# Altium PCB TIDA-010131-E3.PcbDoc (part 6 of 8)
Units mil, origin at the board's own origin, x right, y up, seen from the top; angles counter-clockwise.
Board outline 6889.76 x 5118.11 mil, 6 copper layers (Top Layer, GND Layer, Signal Layer 1, Signal Layer 2, PWR Layer, Bottom Layer), stack 58.5 mil thick; 758 components, 455 nets, 2194 pads, 1156 vias.
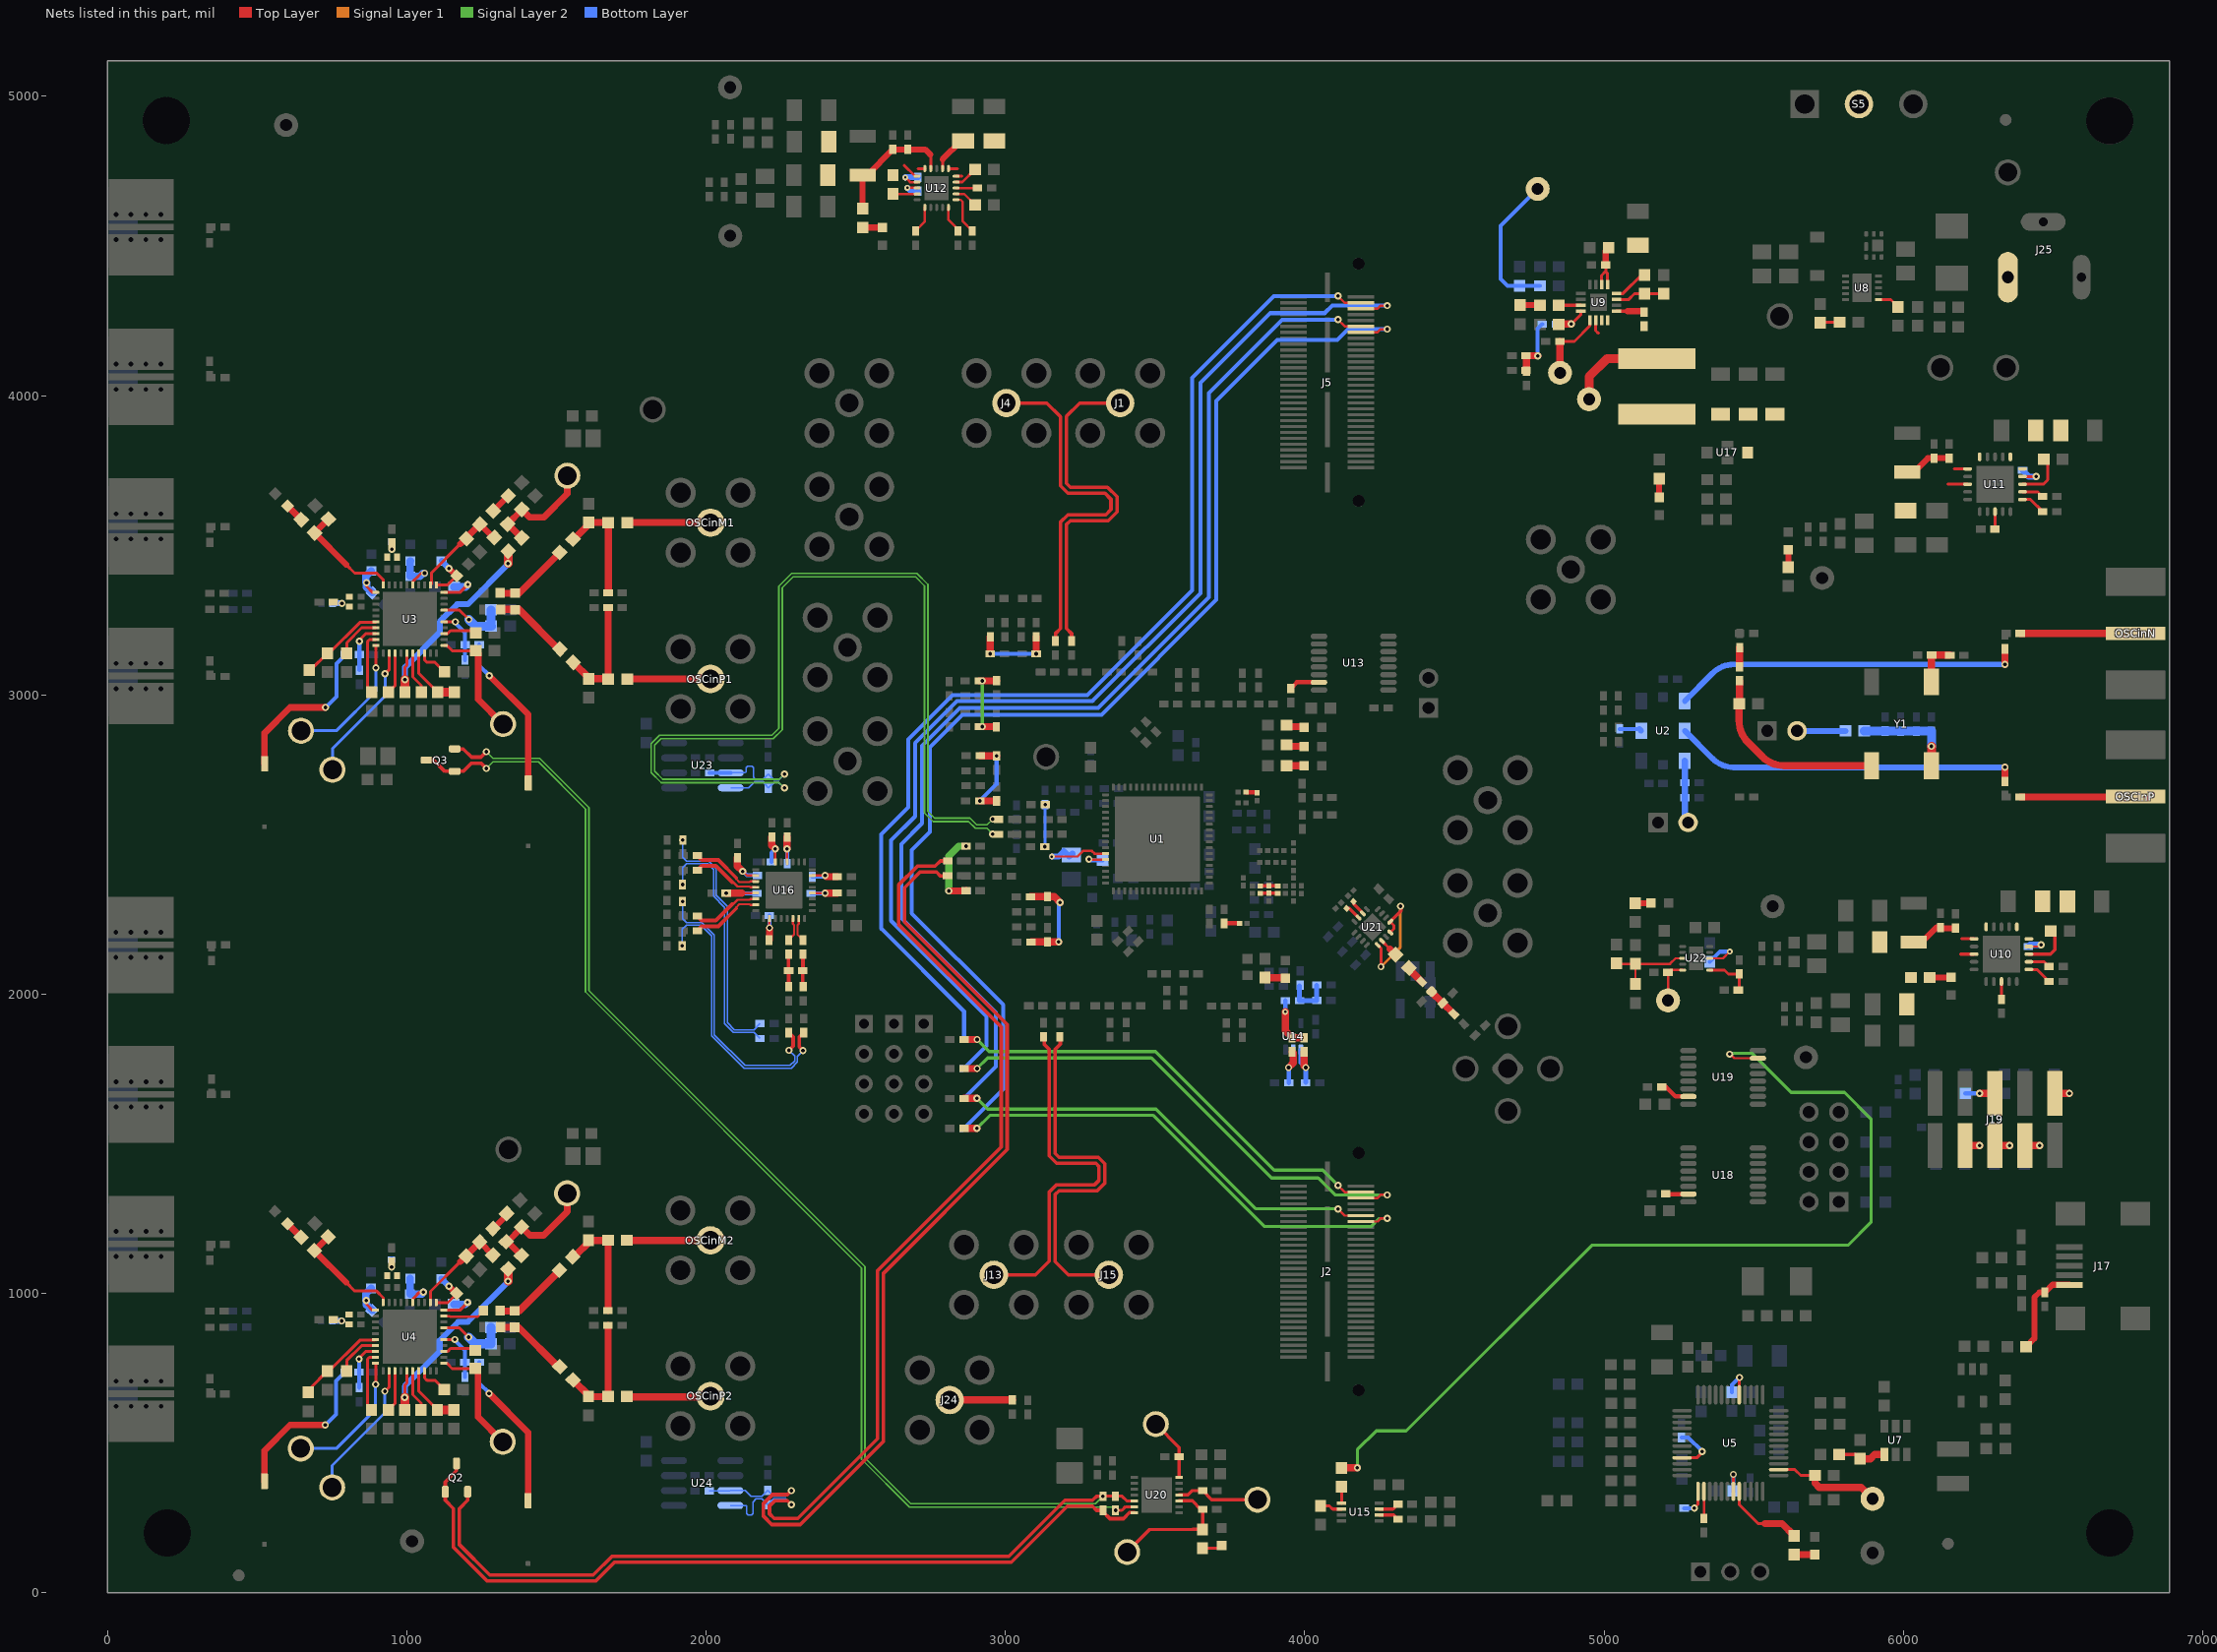
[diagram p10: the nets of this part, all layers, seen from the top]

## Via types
v1: diameter 24, hole 12, Top Layer to Bottom Layer, 726 vias
v2: diameter 32, hole 16, Top Layer to Bottom Layer, 311 vias
v3: diameter 19.68, hole 7.87, Top Layer to Bottom Layer, 117 vias
v4: diameter 25, hole 10, Top Layer to Bottom Layer, 2 vias

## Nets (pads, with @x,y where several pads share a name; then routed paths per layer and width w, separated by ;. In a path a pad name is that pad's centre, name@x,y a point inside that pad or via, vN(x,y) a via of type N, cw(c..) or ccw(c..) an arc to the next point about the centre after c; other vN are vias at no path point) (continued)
LMX_OSCIN2-: C105.2 U4.9 | length 141.3
  Top Layer w8: U4.9@1124.62,924.04 1143.43,924.04 1145.27,922.2 1236.66,922.2 C105.2@1256.79,942.32
LMX_SDO: R207.2 U19.7 | length 3154.5
  Top Layer w8: v1@5419,1802 5435.02,1785.98 U19.7@5514.14,1785.98
  Top Layer w24: R207.2@4123,417.5 4123.5,418 v1(4176,418)
  Signal Layer 2 w10.5: v1(4176,418) 4176,478 4239,541 4339,541 4959,1161 5815,1161 5892,1238 5892,1583 5803.5,1671.5 5625.5,1671.5 5495,1802 v1@5419,1802
  other v1: 5420,1799.5
MUXOUT1: R102.1 R105.2 U3.20 | length 376.8
  Top Layer w9.84: 797.65,3435.55 826.65,3406.55 899.65,3406.55 922.12,3384.07 U3.20@922.12,3367.72
  Top Layer w22: R102.1@738.48,3587.3 R105.2@692.19,3541.01 797.65,3435.55
MUXOUT2: R135.1 R136.2 U4.20 | length 376.8
  Top Layer w9.84: 797.39,1037.14 826.39,1008.14 899.39,1008.14 921.86,985.67 U4.20@921.86,969.32
  Top Layer w22: R135.1@738.22,1188.9 691.93,1142.61 797.39,1037.14
NetC8_2: C8.2 R28.2 | length 37.8
  Top Layer w8: R28.2@3838.57,2674.78 R28.2@3840.57,2672.77
  Top Layer w15: C8.2@3803.57,2674.78 R28.2@3838.57,2674.78
NetC10_2: C10.2 C19.2 C176.2 C177.2 L36.1 Y1.4 | length 340.1
  Top Layer w30: Y1.4@6093.97,2763.39 v1(6093.97,2828.39)
  Bottom Layer w30: L36.1@5869.47,2879.39 5938.73,2879.39 C177.2@5938.97,2879.15 5990.6,2879.15 C176.2@5990.97,2878.77 C19.2@6043.97,2878.77 C10.2@6093.97,2878.77 v1(6093.97,2828.39)
NetC13_1: C13.1 U1.11 | length 281.5
  Top Layer w8: v3@3155,2460 3241,2460 3259.66,2478.66 3288.97,2478.66 3298.23,2469.4 U1.11@3334.6,2469.4
  Bottom Layer w20: v3@3155,2460 3177.79,2460 3195.45,2477.66 3212.45,2460.66 3218.57,2466.78 C13.1@3220.57,2464.78 cw(c3225.07,2464.78) C13.1@3225.07,2469.28
  other v3: 3155,2459.69
NetC14_1: C14.1 U1.12 | length 110.7
  Top Layer w8: v1(3279.07,2451.28) 3279.07,2455.78 3279.57,2456.28 3286.14,2449.72 U1.12@3334.6,2449.72
  Bottom Layer w13.5: v1(3279.07,2451.28) 3282.97,2447.39 C14.1@3325.23,2447.39
NetC17_1: C17.1 R52.2 | length 51
  Top Layer w15: C17.1@3730.86,2236.53 R52.2@3781.84,2236.53
NetC27_1: C27.1 R72.1 R227.2 | length 58.1
  Top Layer w12: C27.1@3851.99,2337.19 3880.79,2337.19 R72.1@3881,2336.98 R227.2@3910.01,2336.99
NetC29_1: C29.1 R271.2 R273.2 | length 58.1
  Top Layer w12: C29.1@3851.99,2361.79 3880.79,2361.79 R273.2@3881,2362 R271.2@3910.01,2361.99
NetC40_1: C40.1 C129.1 L34.1 R226.1 U9.1 U9.2 U9.16 | length 298.7
  Top Layer w9.84: U9.2@4991.82,4371.11 4991.82,4401.04 5005.6,4414.82 C40.1@5005.6,4436.66
  Top Layer w10: 5005.6,4414.82 5011.52,4408.89 U9.1@5011.52,4371.11 ; U9.16@5041.47,4341.16 5063.44,4341.16 5125.44,4403.16 R226.1@5135.97,4403.16
  Top Layer w20: C40.1@5005.6,4436.66 5005.6,4483.79 C129.1@5015.47,4493.66
NetC41_1: C41.1 U9.13 | length 93.7
  Top Layer w10: U9.13@5041.47,4282.06 5078.57,4282.06
  Top Layer w20: 5078.57,4282.06 5131.2,4282.06 C41.1@5133.97,4279.28
NetC41_2: C41.2 L35.1 TP13.1 U9.10 U9.11 U9.12 | length 474.4
  Top Layer w10: U9.10@4972.12,4252.11 4972.12,4217.4 4981.09,4208.44
  Top Layer w30: TP13.1@4950,3988 4950,4063 5010.57,4123.57 L35.1@5176.97,4123.57 L35.1@5276.89,4123.57
NetC42_1: C42.1 C43.1 C73.1 L35.2 U17.1
NetC45_2: C45.2 L11.2 R82.2 R86.2 | length 31.3
  Bottom Layer w20: L11.2@752.31,3305.97 v1(783.6,3305.97)
NetC46_2: C46.2 R83.2 U3.7 | length 233.5
  Top Layer w9.84: U3.7@1124.88,3283.07 1176.5,3283.07 v1(1207.6,3251.97)
  Bottom Layer w30: v1(1207.6,3251.97) 1229.73,3229.85 C46.2@1282.31,3229.85 1282.22,3229.94 R83.2@1282.22,3283.79
NetC47_2: C47.2 R85.2 U3.11 | length 159.7
  Top Layer w10: U3.11@1099.29,3367.72 1137.18,3367.72 C47.2@1173.22,3403.76
  Top Layer w20: v1(1141.53,3422.42) C47.2@1166.65,3397.29
  Bottom Layer w20: R85.2@1116.6,3447.41 1116.6,3447.34 v1(1141.53,3422.42)
NetC49_1: C49.1 R88.2 U3.15 | length 166
  Top Layer w9.84: U3.15@1020.55,3367.72 1020.55,3378.6 1024.39,3382.44 1024.39,3382.9 1031.94,3390.45 1032.4,3390.45 1048.51,3406.56 v1(1059.56,3406.56)
  Bottom Layer w25: R88.2@1012.37,3447.49 1011.7,3446.82 C49.1@1011.7,3395.8 1043.82,3395.8 v1@1054.6,3406.59 ; v1@1054.64,3406.56 v1(1059.56,3406.56)
NetC50_2: C50.2 R87.2 U3.21 | length 141
  Top Layer w10: v1(865.7,3374.55) 865.7,3362.49 886.07,3342.13 U3.21@896.53,3342.13
  Bottom Layer w25: R87.2@881.7,3414.79 863.84,3396.92 863.84,3376.41 v1(865.7,3374.55) 865.7,3360.55 C50.2@885.02,3341.23
NetC55_2: C55.2 R89.1 U3.26 | length 291.3
  Top Layer w9.84: R89.1@671.6,3083.46 679.6,3083.46 C55.2@735.6,3139.46 741.1,3139.46 843.55,3241.91 894.74,3241.91 U3.26@896.53,3243.7
NetC56_2: C56.2 R91.1 U3.37 | length 211.9
  Top Layer w9.84: U3.37@1040.23,3139.37 1040.23,3072.01 C56.2@1103.4,3008.84
  Top Layer w30: C56.2@1103.4,3008.84 R91.1@1158.6,3008.84
NetC58_2: C58.2 R94.1 U3.35 | length 725.3
  Top Layer w9.84: v1(994.1,3050.97) 994.1,3092.21 1000.86,3098.97 U3.35@1000.86,3139.37
  Top Layer w30: C58.2@994.1,3008.84 v1(994.1,3050.97) ; v1@1339.43,3439.71 R94.1@1339.43,3480.07
  Bottom Layer w20: v1(994.1,3050.97) 994.1,3092.54 1110.52,3208.95 1110.52,3244.41 1169,3302.9 1204.46,3302.9 1338.74,3437.17 v1(1338.74,3439.01)
NetC59_1: C59.1 R94.2 R95.2 Vtune_TP1.1 | length 391.6
  Top Layer w22: R94.2@1383.98,3524.62 1337.98,3570.62 R95.2@1337.08,3570.62 1384.43,3617.97 C59.1@1384.43,3620.07 1411.54,3592.97 1457.6,3592.97 1536.7,3672.07 Vtune_TP1.1@1536.7,3732.35
NetC60_1: C60.1 C62.1 R95.1 U3.12 | length 327
  Top Layer w10: U3.12@1079.6,3367.72 1082.56,3370.68 1082.56,3407.92 1179.38,3504.74
  Top Layer w20: C60.1@1244.43,3570.07 R95.1@1288.43,3526.07
  Top Layer w22: 1179.38,3504.74 C60.1@1237.6,3562.97
  Top Layer w30: R95.1@1288.43,3526.07 R95.1@1292.53,3526.07
NetC60_2: C60.2 R96.1 | length 71.1
  Top Layer w20: C60.2@1288.98,3614.62 R96.1@1339.06,3664.7
  Top Layer w30: R96.1@1339.06,3664.7 R96.1@1339.33,3664.7
NetC61_2: C61.2 L12.2 R93.1 R97.2 | length 26
  Bottom Layer w20: v1(950.28,3486.06) L12.2@950.28,3512.05
NetC63_2: C63.2 U3.10 | length 138.8
  Top Layer w10: U3.10@1124.88,3342.13 1177.59,3342.13 v4(1203.7,3368.25)
  Bottom Layer w25: C63.2@1157.7,3360.69 1196.15,3360.69 v4(1203.7,3368.25)
NetC65_1: C65.1 U3.36 | length 142.1
  Top Layer w9.84: U3.36@1020.55,3139.37 1020.55,3060.03 1048.5,3032.07 C65.1@1048.5,3008.84
NetC66_2: C66.2 U3.38 | length 105.8
  Top Layer w9.84: U3.38@1059.92,3139.37 1059.92,3116.28 1067.65,3108.55 1094.61,3108.55 C66.2@1126.31,3076.85
NetC67_1: C67.1 U3.29 | length 211
  Top Layer w9.84: C67.1@883,3008.84 872.73,3008.84 869.6,3011.97 869.6,3178.97 875.28,3184.65 U3.29@896.53,3184.65
NetC68_1: C68.1 U3.3 | length 116.7
  Top Layer w9.84: U3.3@1124.88,3204.33 1136.22,3204.33 1146.35,3214.47 1223.09,3214.47 C68.1@1230.21,3207.35 C68.1@1227.2,3204.33
NetC69_2: C69.2 U3.27 | length 152.5
  Top Layer w9.84: C69.2@799.7,3139.05 799.7,3174.07 849.65,3224.02 U3.27@896.53,3224.02
NetC70_2: C70.2 U3.33 | length 139.7
  Top Layer w9.84: C70.2@939.4,3008.84 961.49,3030.93 U3.33@961.49,3139.37
NetC71_1: C71.1 R107.2 R109.2 | length 252.3
  Top Layer w24: C71.1@1313.86,3285.55 1374.26,3285.55 R107.2@1509.99,3149.82
NetC72_1: C72.1 R109.1 R112.1 | length 251.9
  Top Layer w24: C72.1@1312.16,3340.72 1313.66,3339.22 1375.26,3339.22 R112.1@1508.31,3472.27
NetC74_1: C74.1 TP15.1 U9.9 | length 245.9
  Top Layer w10: C74.1@4852.62,4181 4901,4181 4952.42,4232.42 U9.9@4952.42,4252.11
  Top Layer w24: C74.1@4852.62,4181 4852.62,4076.38 TP15.1@4853,4076
NetC75_1: C75.1 R231.1 | length 65.7
  Top Layer w20: C75.1@4719.97,4302.16 4784.98,4302.16 R231.1@4785.48,4301.66
NetC78_2: C78.2 L13.2 R115.2 R119.2 | length 31.3
  Bottom Layer w20: L13.2@751.55,908.07 v1(782.85,908.07)
NetC79_2: C79.2 R116.2 U4.7 | length 233.5
  Top Layer w9.84: U4.7@1124.62,884.67 1176.24,884.67 v1(1206.85,854.07) v1@1207.35,853.57
  Bottom Layer w30: v1(1206.85,854.07) 1228.97,831.94 C79.2@1281.55,831.94 1281.46,832.04 R116.2@1281.46,885.89
NetC80_2: C80.2 R118.2 U4.11 | length 159.7
  Top Layer w10: U4.11@1099.03,969.32 1136.92,969.32 C80.2@1172.96,1005.36
  Top Layer w20: v1@1141.27,1024.02 C80.2@1166.39,998.89
  Bottom Layer w20: R118.2@1115.85,1049.51 R118.2@1115.85,1049.44 v1(1140.77,1024.52)
NetC82_1: C82.1 R121.2 U4.15 | length 156.8
  Top Layer w9.84: U4.15@1020.29,969.32 1020.29,981.25 1023.63,984.6 1023.63,985 1042.63,1004 v1(1056,1004)
  Bottom Layer w25: R121.2@1011.62,1049.59 1010.95,1048.92 C82.1@1010.95,997.9 1049.9,997.9 v1(1056,1004)
NetC83_2: C83.2 R120.2 U4.21 | length 141
  Top Layer w10: v1@865.45,976.14 865.45,964.09 885.81,943.73 U4.21@896.27,943.73
  Bottom Layer w25: R120.2@880.95,1016.88 863.08,999.02 863.08,978.51 v1(864.95,976.64) 864.95,962.64 C83.2@884.26,943.33
NetC88_2: C88.2 R122.1 U4.26 | length 291.3
  Top Layer w9.84: R122.1@671.35,685.06 679.35,685.06 735.35,741.06 740.84,741.06 843.29,843.51 894.48,843.51 U4.26@896.27,845.3
NetC89_2: C89.2 R124.1 U4.37 | length 211.9
  Top Layer w9.84: U4.37@1039.97,740.97 1039.97,673.61 C89.2@1103.15,610.44
  Top Layer w30: C89.2@1103.15,610.44 R124.1@1158.35,610.44
NetC91_2: C91.2 R127.1 U4.35 | length 722.9
  Top Layer w9.84: v1@993.85,652.57 993.85,693.81 1000.6,700.57 U4.35@1000.6,740.97
  Top Layer w30: C91.2@993.85,610.44 v1@993.85,652.57 ; v1@1339.17,1041.31 R127.1@1339.17,1081.67
  Bottom Layer w20: v1(993.35,653.07) 993.35,689.97 1109.76,806.38 1109.76,842.51 1172.24,905 1203.7,905 1337.98,1039.27 v1(1337.98,1041.11)
NetC92_1: C92.1 R127.2 R128.2 Vtune_TP2.1 | length 391.6
  Top Layer w22: R127.2@1383.72,1126.22 1337.72,1172.22 1336.82,1172.22 1384.17,1219.57 1384.17,1221.67 1411.28,1194.57 1457.35,1194.57 1536.45,1273.67 Vtune_TP2.1@1536.45,1333.94
NetC93_1: C93.1 C95.1 R128.1 U4.12 | length 327
  Top Layer w10: U4.12@1079.34,969.32 1079.34,1006.56 1179.12,1106.34
  Top Layer w20: C93.1@1244.17,1171.67 R128.1@1287.67,1128.17 R128.1@1288.17,1127.67
  Top Layer w22: 1179.12,1106.34 C93.1@1237.35,1164.57
  Top Layer w30: R128.1@1288.17,1127.67 R128.1@1292.27,1127.67
NetC93_2: C93.2 R129.1 | length 71.1
  Top Layer w20: C93.2@1288.72,1216.22 R129.1@1338.8,1266.3
  Top Layer w30: R129.1@1338.8,1266.3 R129.1@1339.07,1266.3
NetC94_2: C94.2 L14.2 R126.1 R130.2 | length 26
  Bottom Layer w20: v1(949.52,1088.16) L14.2@949.52,1114.15
NetC96_2: C96.2 U4.10 | length 138.8
  Top Layer w10: U4.10@1124.62,943.73 1177.33,943.73 v4@1203.45,969.84
  Bottom Layer w25: C96.2@1156.94,962.79 1195.39,962.79 v4(1202.95,970.34)
NetC98_1: C98.1 U4.36 | length 142.1
  Top Layer w9.84: U4.36@1020.29,740.97 1020.29,661.62 1048.25,633.67 C98.1@1048.25,610.44
NetC99_2: C99.2 U4.38 | length 105.8
  Top Layer w9.84: U4.38@1059.66,740.97 1059.66,717.88 1067.39,710.14 1094.35,710.14 C99.2@1126.05,678.44
NetC100_1: C100.1 U4.29 | length 211
  Top Layer w9.84: C100.1@882.75,610.44 872.47,610.44 869.35,613.57 869.35,780.57 875.03,786.25 U4.29@896.27,786.25
NetC101_1: C101.1 U4.3 | length 116.7
  Top Layer w9.84: U4.3@1124.62,805.93 1135.96,805.93 1146.09,816.07 1222.83,816.07 1229.95,808.94 C101.1@1226.94,805.93
NetC102_2: C102.2 U4.27 | length 152.5
  Top Layer w9.84: C102.2@799.45,740.65 799.45,775.67 849.4,825.62 U4.27@896.27,825.62
NetC103_2: C103.2 U4.33 | length 139.7
  Top Layer w9.84: C103.2@939.15,610.44 961.23,632.53 U4.33@961.23,740.97
NetC104_1: C104.1 R140.2 R142.2 | length 252.3
  Top Layer w24: C104.1@1313.6,887.14 1374,887.14 R140.2@1509.73,751.42
NetC105_1: C105.1 R142.1 R145.1 | length 251.9
  Top Layer w24: C105.1@1311.9,942.32 1313.4,940.82 1375,940.82 R145.1@1508.06,1073.87
NetC113_2: C113.2 U5.38 VCCCORE.1 | length 369
  Top Layer w10: U5.38@5583.62,411.44 5637.78,411.44 5657.2,392.02 C113.2@5704.7,392.02
  Top Layer w24: C113.2@5704.7,392.02 5704.7,366.27 5718.96,352.02 5859.2,352.02 VCCCORE.1@5897.2,314.02
NetC122_1: C122.1 J17.1 R148.1 | length 310.6
  Top Layer w20: R148.1@6410.5,822 6438,849.5 6438,987.09 6454.54,1003.62 C122.1@6473,1003.62 6498.39,1029.01 J17.1@6554.77,1029.01
NetC133_1: C133.1 U8.1 | length 74.9
  Top Layer w10: U8.1@5917.3,4320.64 5958.05,4320.64 C133.1@5982.18,4296.51
NetC134_1: C134.1 L28.1 L30.2 U10.13 U10.15 U10.16 | length 161.9
  Top Layer w12: U10.13@6419.43,2133.66 6491.94,2133.66 6506.57,2148.29 6506.57,2197.32 C134.1@6492.64,2211.25
NetC135_1: C135.1 C136.1 C137.1 L20.1 L23.1 R223.2 U10.1 U10.3 U10.20 | length 246.5
  Top Layer w10: 6191.34,2133.66 U10.3@6236.36,2133.66 ; 6195.69,2184.84 U10.1@6236.36,2184.84
  Top Layer w20: C137.1@6034.43,2174.29 6062.39,2174.29 6110.72,2222.62 C136.1@6124.43,2222.62 6126.42,2220.63 C135.1@6174.43,2220.63
NetC138_1: C138.1 L29.1 L31.2 U11.13 U11.15 U11.16 | length 165.1
  Top Layer w10: U11.13@6398,3703.91 6467.99,3703.91 6482.69,3718.61 6482.69,3774.31 C138.1@6469.5,3787.5
NetC139_1: C139.1 C140.1 C141.1 L21.1 U11.1 U11.3 U11.20 | length 270.3
  Top Layer w10: 6148.54,3703.91 U11.3@6214.93,3703.91 ; 6170.19,3755.09 U11.1@6214.93,3755.09
  Top Layer w20: C141.1@6013,3744.54 6035.98,3744.54 6082.32,3790.88 C140.1@6103,3790.88 C139.1@6153,3790.88
NetC150_1: C150.1 U10.14 | length 87.3
  Top Layer w8: U10.14@6419.43,2159.25 6454.25,2159.25 v1(6460,2165)
  Bottom Layer w20: C150.1@6418.06,2159.25 6423.81,2165 v1(6460,2165)
NetC151_1: C151.1 U11.14 | length 99.9
  Top Layer w10: U11.14@6398,3729.5 v1(6444,3729.5)
  Bottom Layer w20: C151.1@6398.62,3750 6419.12,3729.5 v1(6444,3729.5)
NetC154_1: C154.1 L32.1 L33.2 U12.14 U12.15 U12.16 U12.17 | length 254.7
  Top Layer w10: U12.17@2790.15,4758.63 2790.15,4789.73 ; U12.16@2809.83,4758.63 2840.07,4758.63 ; U12.14@2835.42,4713.35 2856.6,4713.35 C154.1@2898.5,4755.26 ; U12.15@2835.42,4733.04 2854.04,4733.04
  Top Layer w20: 2790.15,4789.73 2851.59,4851.17 L32.1@2859,4851.17
NetC155_1: C155.1 C156.1 C157.1 C162.1 L25.1 L27.1 R224.2 R294.2 U12.1 U12.2 U12.19 U12.20 | length 598.1
  Top Layer w8: v3(2665.79,4729.15) 2681.59,4713.35 U12.2@2705.5,4713.35
  Top Layer w9.84: 2662,4769.37 2698.33,4733.04 U12.1@2705.5,4733.04 ; 2748.72,4805.98 2750.78,4803.92 U12.19@2750.78,4758.63
  Top Layer w10: 2708.46,4758.63 U12.20@2731.09,4758.63
  Top Layer w20: R224.2@2523,4624.5 C157.1@2523,4736.3 2537.66,4736.3 C156.1@2624,4822.64 C155.1@2674,4822.64 2732.06,4822.64 2748.72,4805.98
  Bottom Layer w20: v3(2665.79,4729.15) 2666.41,4729.78 C162.1@2707.79,4729.78
NetC162_2: C162.2 U12.3 | length 72.7
  Top Layer w8: v3(2672.79,4694.15) 2705.02,4694.15 U12.3@2705.5,4693.67
  Bottom Layer w20: v3(2672.79,4694.15) 2684.41,4682.53 C162.2@2707.79,4682.53
NetC166_1: C166.1 R233.1 U16.2 | length 155.8
  Top Layer w8: v1(2122.82,2410.41) 2136.62,2396.61 U16.2@2166.12,2396.61
  Top Layer w24: R233.1@2104.82,2455.78 2104.82,2428.41 v1(2122.82,2410.41)
  Bottom Layer w13.5: v1(2122.82,2410.41) 2136.32,2396.91 C166.1@2171.2,2396.91
NetC167_2: C167.2 R239.1 U16.10 | length 113.8
  Top Layer w8: U16.10@2211.39,2252.91 2211.39,2221.83 v1(2211.82,2221.41)
  Top Layer w24: R239.1@2210.82,2180.53 2211.82,2181.53 v1(2211.82,2221.41)
  Bottom Layer w13.5: v1(2211.82,2221.41) C167.2@2211.82,2262.28
NetC168_1: C168.1 R234.1 U16.5 | length 201.7
  Top Layer w8: 2118.96,2337.55 U16.5@2166.12,2337.55
  Top Layer w24: v1(2067.44,2337.41) 2067.59,2337.55 2118.96,2337.55
  Bottom Layer w13.5: v1(2067.44,2337.41) 2067.94,2336.91 C168.1@2170.2,2336.91
NetC169_2: C169.2 R238.1 U16.28 | length 133.4
  Top Layer w8: U16.28@2270.45,2441.88 2270.45,2485.04 v1(2270.82,2485.41)
  Top Layer w24: v1(2270.82,2485.41) R238.1@2270.82,2525.28
  Bottom Layer w13.5: C169.2@2270.82,2435.53 v1(2270.82,2485.41)
NetC170_1: C170.1 R235.1 U16.20 | length 129.7
  Top Layer w8: U16.20@2355.09,2337.55 v1(2397.62,2337.55)
  Top Layer w24: v1(2397.62,2337.55) 2397.97,2337.91 R235.1@2438.2,2337.91
  Bottom Layer w13.5: C170.1@2351.44,2336.91 2396.97,2336.91 v1(2397.62,2337.55)
NetC171_1: C171.1 R236.1 U16.23 | length 128.8
  Top Layer w6.5: v1(2397.62,2396.61) v1@2401.32,2392.91
  Top Layer w8: U16.23@2355.09,2396.61 v1(2397.62,2396.61)
  Top Layer w24: v1@2401.32,2392.91 R236.1@2438.2,2392.91
  Bottom Layer w4.25: v1@2393.68,2392.67 v1(2397.62,2396.61)
  Bottom Layer w13.5: C171.1@2355.09,2392.67 v1@2393.68,2392.67
NetC172_1: C172.1 R237.1 U16.30 | length 136.7
  Top Layer w8: U16.30@2231.08,2441.88 v1@2231.08,2485.04
  Top Layer w24: R237.1@2219.82,2524.78 2219.82,2497.04 v1(2231.45,2485.41)
  Bottom Layer w13.5: C172.1@2218.44,2441.41 2218.44,2472.4 v1(2231.45,2485.41)
NetC173_1: C173.1 R244.2 R249.2 | length 109.1
  Top Layer w12: R244.2@2275.82,2024.53 2276.2,2024.91 R249.2@2276.2,2078.91 2275.82,2079.28 C173.1@2275.82,2133.28
NetC173_2: C173.2 U16.14 | length 81.3
  Top Layer w7: C173.2@2275.82,2180.53 2293.73,2198.44 2293.73,2231 2290.13,2234.59 U16.14@2290.13,2252.91
NetC174_1: C174.1 R249.1 R250.2 | length 109.5
  Top Layer w12: C174.1@2323.82,2133.28 2323.82,2079.28 R249.1@2323.44,2078.91 2323.44,2025.91 R250.2@2324.82,2024.53
NetC174_2: C174.2 U16.15 | length 81.2
  Top Layer w7: U16.15@2309.82,2252.91 2309.82,2234.59 2306.23,2231 2306.23,2198.12 C174.2@2323.82,2180.53
NetC175_1: C175.1 R232.2 U9.8 | length 151.1
  Top Layer w10: R232.2@4848.47,4237.66 R232.2@4849.97,4237.66 ; v1(4891,4239) 4922.47,4270.47 U9.8@4922.47,4282.06
  Top Layer w24: R232.2@4848.47,4237.66 4849.81,4239 v1(4891,4239)
  Bottom Layer w13.5: C175.1@4840.62,4239 v1(4891,4239)
NetC175_2: C175.2 R259.1 R260.2 R261.1 | length 203
  Top Layer w15: R259.1@4739.62,4133 R259.1@4741,4131.62
  Top Layer w24: R259.1@4739.62,4133 v1(4778.32,4132.97) ; R260.2@4741,4081.62 R259.1@4741,4131.62
  Bottom Layer w13.5: v1(4778.32,4132.97) 4778.32,4223.94 C175.2@4793.38,4239
NetC178_2: C178.2 R299.1 Y1.1 | length 151.3
  Top Layer w24: Y1.1@6093.97,3043.39 6093.97,3132.77 C178.2@6094.6,3133.39 6154.62,3133.39 R299.1@6155.35,3132.66
NetC179_1: C179.1 R33.1 | length 64.1
  Top Layer w24: R33.1@5452.97,3094.28 5453.07,3094.38 C179.1@5453.07,3158.37
NetC180_2: C180.2 U12.12 | length 78.2
  Top Layer w8: U12.12@2835.42,4673.98 2862.02,4673.98 C180.2@2898.5,4637.5
NetC181_2: C181.2 U12.13 | length 71
  Top Layer w8: U12.13@2835.42,4693.67 2906.21,4693.67 C181.2@2906.38,4693.5
NetC187_2: C187.2 C188.2 J16.2 U2.6@5269.91,2779.81 | length 206.3
  Bottom Layer w20: U2.6@5269.91,2779.81 5270.35,2779.36 C188.2@5270.35,2706.66 C187.2@5270.35,2656.66 J16.2@5270.35,2573.66
NetC203_1: C203.1 Q2.1 Q2.3 U20.7 | length 2760
  Top Layer w12: Q2.3@1166.1,432 1166.1,407.76 1128.7,370.36 Q2.1@1128.7,337.51 1128.7,308.83 1156.1,281.43 1156.1,249.76 1156.1,151.9 1269,39 1631.28,39 1694.28,102 3020.28,102 3207.28,289 3291.57,289 3305.19,275.38 C203.1@3326,275.38 3326,271 3349.37,247.63 3394.63,247.63 3414.74,267.74 U20.7@3430.77,267.74
NetC203_2: C203.2 C204.2 Q2.2 Q3.2 U20.5 | length 6568.6
  Top Layer w9.8: C203.2@3326,322.62 C204.2@3368,322.62 3389.88,322.62 3405.39,307.11 U20.5@3430.77,307.11
  Top Layer w12: Q3.2@1160.24,2819.4 1188.93,2819.4 1216.33,2792 1248,2792 v1(1266,2810) ; Q2.2@1203.5,337.51 1203.5,308.83 1176.1,281.43 1176.1,160.19 1277.28,59 1623,59 1686,122 3012,122 3199,309 3291.57,309 3305.19,322.62 C203.2@3326,322.62
  Signal Layer 2 w5.5: v1(1266,2810) 1288.25,2787.75 1444.51,2787.75 1608.5,2623.76 1608.5,2012.5 2531,1090 2531,451 2684,298 3301.31,298 v1(3326,322.69)
NetC204_1: C204.1 Q3.1 Q3.3 U20.6 | length 4181.9
  Top Layer w7: v1(3368,275.45) v1(3368,275.45)
  Top Layer w9.8: v1(3368,275.45) 3389.38,275.38 3401.43,287.43 U20.6@3430.77,287.43
  Top Layer w12: Q3.3@1065.76,2782 1090,2782 1127.4,2744.6 1188.93,2744.6 1216.33,2772 1248,2772 v1(1266,2754)
  Signal Layer 2 w5.5: v1(1266,2754) 1288.25,2776.25 1439.75,2776.25 1597,2619 1597,2007.74 2519.5,1085.24 2519.5,446.24 2679.24,286.5 3356.95,286.5 v1(3368,275.45)
NetC207_1: C207.1 R331.1 R332.2 U22.3 | length 296.7
  Top Layer w8: R331.1@5042,2102.5 5043,2101.5 C207.1@5105,2101.5 ; R332.2@5105,2033.5 C207.1@5105,2101.5 ; U22.3@5262.72,2119.8 5238.8,2119.8 5220.5,2101.5 C207.1@5105,2101.5
NetC208_1: C208.1 U22.8 | length 156.8
  Top Layer w8: U22.8@5353.27,2119.8 5397.8,2119.8 v3(5420,2142)
  Bottom Layer w13.5: C208.1@5353.27,2107.99 5387.28,2142 v3(5420,2142)
NetC210_1: C210.1 R322.1 | length 64.6
  Top Layer w24: C210.1@4349.27,2087.73 C210.1@4348.27,2087.73 4348.27,2084.08 R322.1@4390.64,2041.71
NetC210_2: C210.2 U21.2 | length 64.7
  Top Layer w10: U21.2@4258.01,2178.07 4285,2151.08 4285,2151
  Top Layer w24: 4285,2151 C210.2@4303.73,2132.27
NetCE_TP1_1: CE_TP1.1 R90.2 U3.1 | length 395.5
  Top Layer w9.84: U3.1@1124.88,3164.96 1134.61,3164.96 1152.23,3147.35 R90.2@1230.21,3147.35
  Top Layer w22: R90.2@1230.21,3147.35 1239,3138.55 1239,2985.05 CE_TP1.1@1321.7,2902.35
NetCE_TP2_1: CE_TP2.1 R123.2 U4.1 | length 400.2
  Top Layer w9.84: U4.1@1124.62,766.56 1134.35,766.56 1151.97,748.94 R123.2@1238,748.94
  Top Layer w22: R123.2@1238,748.94 1238,587.39 CE_TP2.1@1320.95,504.44 CE_TP2.1@1321.45,503.94
NetD1_1: D1.1 R77.2 | length 61
  Top Layer w24: R77.2@3939.53,2832.95 3944.47,2828 D1.1@3998.47,2828
NetD2_1: D2.1 R78.2 | length 59
  Top Layer w24: R78.2@3937.48,2893.78 D2.1@3996.46,2893.78
NetD3_1: D3.1 R79.2 | length 68.8
  Top Layer w24: R79.2@3867.19,2054.9 3933.16,2054.9 D3.1@3935.19,2052.87
NetD4_1: D4.1 R80.2 | length 59
  Top Layer w24: R80.2@3939.37,2763.58 D4.1@3998.34,2763.58
NetD5_1: D5.1 R105.1 | length 64
  Top Layer w22: D5.1@602.41,3630.79 R105.1@647.65,3585.55
NetD6_1: D6.1 R136.1 | length 64
  Top Layer w22: D6.1@602.15,1232.39 R136.1@647.39,1187.15
NetD10_1: D10.1 R217.1 | length 69
  Top Layer w24: R217.1@5635.2,127.52 D10.1@5704.17,127.52
NetD11_1: D11.1 R220.1 | length 63
  Top Layer w20: D11.1@5184.3,3659.87 R220.1@5184.3,3722.85
NetD13_1: D13.1 R222.1 | length 59
  Top Layer w20: R222.1@5615.85,3426.48 D13.1@5615.85,3485.45
NetD14_1: D14.1 R223.1 | length 71.2
  Top Layer w20: R223.1@6088.36,2055.48 6158.84,2055.48 D14.1@6159.36,2056.01
NetD15_1: D15.1 R224.1 | length 66.7
  Top Layer w20: R224.1@2523,4561.5 2589.13,4561.5 D15.1@2589.5,4561.13
NetD16_2: D16.2 R319.2 | length 67.5
  Top Layer w11: R319.2@3658.51,148.74 3714.02,148.74 D16.2@3722.51,157.24
NetD17_1: D17.1 R342.1 | length 52.7
  Top Layer w20: R342.1@5104,2304.5 5155.98,2304.5 D17.1@5156.47,2304
NetJ1_1: J1.1 R3.1 | length 1242.3
  Top Layer w12: R3.1@3221.17,3180.02 3221.17,3204.77 3204.27,3221.67 3204.27,3569.46 3216.82,3582 3344,3582 3373,3611 3373,3662 3341,3694 3216.82,3694 3204.27,3706.54 3204.27,3930.77 3248.5,3975 J1.1@3383.5,3975
NetJ2_4: J2.4 R252.2 | length 1537.4
  Top Layer w8: v1(4110.97,1361.32) 4133.51,1338.78 J2.4@4188.32,1338.78
  Top Layer w24: R252.2@2862.1,1848.66 v1(2905.47,1848.66)
  Signal Layer 2 w10.5: v1(2905.47,1848.66) 2946.13,1808 3502,1808 3898,1412 4060.29,1412 v1(4110.97,1361.32)
NetJ2_6: J2.6 R254.2 | length 1710
  Top Layer w8: J2.6@4188.32,1319.09 4243.12,1319.09 4253.34,1329.32 v1(4275.97,1329.32)
  Top Layer w24: R254.2@2862.1,1751.66 v1(2905.47,1751.66)
  Signal Layer 2 w10.5: v1(2905.47,1751.66) 2940.81,1787 3488,1787 3889,1386 4045,1386 4101.68,1329.32 v1(4275.97,1329.32)
NetJ2_12: J2.12 R256.2 | length 1488.8
  Top Layer w8: v1(4110.97,1282.58) 4133.51,1260.04 J2.12@4188.32,1260.04
  Top Layer w24: R256.2@2861.72,1651.66 v1(2905.1,1651.66)
  Signal Layer 2 w10.5: v1(2905.1,1651.66) 2940.76,1616 3503.83,1616 3837.26,1282.58 v1(4110.97,1282.58)
NetJ2_14: J2.14 R258.2 | length 1689.2
  Top Layer w8: J2.14@4188.32,1240.35 4243.12,1240.35 4253.34,1250.58 v1(4275.97,1250.58)
  Top Layer w24: R258.2@2861.72,1551.66 v1(2905.1,1551.66)
  Signal Layer 2 w10.5: v1(2905.1,1551.66) 2948.44,1595 3494.5,1595 3866,1223.5 4221.5,1223.5 4248.58,1250.58 v1(4275.97,1250.58)
NetJ4_1: J4.1 R6.1 | length 1243
  Top Layer w12: J4.1@3003.5,3975 3138.5,3975 3184.27,3929.23 3184.27,3698.26 3208.53,3674 3332.72,3674 3353,3653.72 3353,3619.28 3335.72,3602 3208.53,3602 3184.27,3577.74 3184.27,3221.67 3167.37,3204.77 R6.1@3167.37,3180.02
NetJ5_4: J5.4 R251.2 | length 3706.3
  Top Layer w8: v1(4110.97,4332.66) 4133.51,4310.12 J5.4@4188.32,4310.12
  Bottom Layer w13.5: R251.2@2862.1,1848.66 2862.1,1942.4 2585.2,2219.3 2585.2,2534.2 2675,2624 2675,2851 2823.5,2999.5 3274.5,2999.5 3624.22,3349.22 3624.22,4058.91 3896.97,4331.66 4109.97,4331.66 v1(4110.97,4332.66)
NetJ5_6: J5.6 R253.2 | length 3971.1
  Top Layer w8: J5.6@4188.32,4290.44 4243.12,4290.44 4253.34,4300.66 v1(4275.97,4300.66)
  Bottom Layer w13.5: R253.2@2861.72,1751.66 2937.47,1827.42 2937.47,1926.03 2618,2245.5 2618,2514 2698,2594 2698,2839 2838,2979 3291,2979 3651.97,3339.97 3651.97,4042.66 3884.97,4275.66 4066.97,4275.66 4091.97,4300.66 v1(4275.97,4300.66)
NetJ5_12: J5.12 R255.2 | length 3847.3
  Top Layer w8: v1(4110.97,4253.92) 4133.51,4231.38 J5.12@4188.32,4231.38
  Bottom Layer w13.5: R255.2@2861.72,1651.66 2968.03,1757.97 2968.03,1938.47 2652,2254.5 2652,2501 2722,2571 2722,2830 2848,2956 3309.5,2956 3679.97,3326.47 3679.97,4008.66 3925.23,4253.92 v1(4110.97,4253.92)
NetJ5_14: J5.14 R257.2 | length 4066.6
  Top Layer w8: J5.14@4188.32,4211.7 4243.12,4211.7 4253.34,4221.92 v1(4275.97,4221.92)
  Bottom Layer w13.5: R257.2@2861.72,1551.66 2992.5,1682.44 2992.5,1964.5 2687,2270 2687,2481 2748,2542 2748,2825 2857,2934 3321,2934 3704.97,3317.97 3704.97,3981.66 3908.97,4185.66 4108.97,4185.66 4145.23,4221.92 v1(4275.97,4221.92)
NetJ8_2: J8.2 L36.2 | length 175.4
  Bottom Layer w20: J8.2@5631.34,2878.66 5632.08,2879.39 L36.2@5806.48,2879.39
NetJ13_1: J13.1 R54.1 | length 1248.9
  Top Layer w12: J13.1@2961.68,1062.23 3100.68,1062.23 3146.45,1108.01 3146.45,1338.98 3170.71,1363.23 3298.23,1363.23 3312,1377 3312,1425.51 3302.28,1435.23 3170.71,1435.23 3146.45,1459.49 3146.45,1815.57 3129.55,1832.47 R54.1@3129.55,1857.22
NetJ15_1: J15.1 R56.1 | length 1244.2
  Top Layer w12: R56.1@3183.35,1857.22 3183.35,1832.47 3166.45,1815.57 3166.45,1467.78 3178.99,1455.23 3310.56,1455.23 3332,1433.8 3332,1368.72 3306.52,1343.23 3178.99,1343.23 3166.45,1330.69 3166.45,1106.46 3210.68,1062.23 J15.1@3345.68,1062.23
NetJ18_1: J18.1 R349.2 | length 545.9
  Top Layer w22: J18.1@525,2770 525,2872.69 610.31,2958 v1(729,2958)
  Bottom Layer w13.5: v1(729,2958) 765,2994 765,3104.87 R349.2@794.76,3134.62
NetJ19_1: J19.1 R306.2 | length 102.2
  Top Layer w24: J19.1@6506,1669 v1(6555,1669)
  Bottom Layer w13.5: R306.2@6502,1668.5 R306.2@6505,1668.5 6554.5,1668.5 v1(6555,1669)
NetJ19_4: J19.4 R303.2 | length 100.6
  Top Layer w24: J19.4@6406,1494 v1(6455,1494)
  Bottom Layer w13.5: R303.2@6404,1495.5 6453.5,1495.5 v1(6455,1494)
NetJ19_5: J19.5 R307.2 | length 99.2
  Top Layer w24: v1(6255,1669) J19.5@6306,1669
  Bottom Layer w13.5: R307.2@6207,1668.5 6254.5,1668.5 v1(6255,1669)
NetJ19_6: J19.6 R304.2 | length 100.6
  Top Layer w24: J19.6@6306,1494 v1(6355,1494)
  Bottom Layer w13.5: R304.2@6304,1495.5 6353.5,1495.5 v1(6355,1494)
NetJ19_8: J19.8 R302.2 | length 99.6
  Top Layer w24: J19.8@6206,1494 v1(6255,1494)
  Bottom Layer w13.5: R302.2@6205,1495.5 6253.5,1495.5 v1(6255,1494)
NetJ24_1: J24.1 R323.1 | length 209
  Top Layer w24: J24.1@2814,644 R323.1@3023,644
NetJ25_1: J25.1 S5.2
NetJ26_1: J26.1 R348.2 | length 529.4
  Top Layer w22: v1(1276,3064) 1406,2934 J26.1@1406,2706.08
  Bottom Layer w13.5: R348.2@1242.24,3167.62 1242.24,3097.76 v1(1276,3064)
NetJ27_1: J27.1 R353.2 | length 545.9
  Top Layer w22: J27.1@525,372.49 525,475.19 610.31,560.49 v1@729,560.49
  Bottom Layer w13.5: v1(727.85,560.49) 763.85,596.49 763.85,707.36 R353.2@793.6,737.12
NetJ28_1: J28.1 R352.2 | length 529.4
  Top Layer w22: v1(1275.24,666.1) 1405.24,536.1 J28.1@1405.24,308.18
  Bottom Layer w13.5: R352.2@1242.24,769.72 1242.24,699.85 v1@1276,666.1
NetOSCinM1_1: OSCinM1.1 R111.1 | length 278.5
  Top Layer w24: R111.1@1736.2,3575.85 OSCinM1.1@2014.7,3575.85
NetOSCinM2_1: OSCinM2.1 R144.1 | length 278.5
  Top Layer w24: R144.1@1735.94,1177.44 OSCinM2.1@2014.45,1177.44
NetOSCinN_1: OSCinN.1 R37.2 | length 385.5
  Top Layer w24: R37.2@6390.5,3205.5 R37.2@6390.41,3205.59 OSCinN.1@6775.79,3205.59
NetOSCinP1_1: OSCinP1.1 R106.1 | length 278.5
  Top Layer w24: R106.1@1736.2,3053.15 OSCinP1.1@2014.7,3053.15
NetOSCinP2_1: OSCinP2.1 R139.1 | length 278.5
  Top Layer w24: R139.1@1735.94,654.74 OSCinP2.1@2014.45,654.74
NetOSCinP_1: OSCinP.1 R39.2 | length 383.6
  Top Layer w24: R39.2@6390.39,2658.59 OSCinP.1@6773.97,2658.59
NetR13_1: R13.1 R14.1 R336.1 R337.2 | length 268
  Top Layer w24: R13.1@2949.93,3137.03 v1(2949.57,3137.4) 2949.57,3193.57 R336.1@2950,3194 ; R337.2@3103,3194 3102.81,3193.81 v1(3102.81,3137.4) R14.1@3103.17,3137.76
  Bottom Layer w13.5: v1(2949.57,3137.4) 2979.42,3137.4 2979.78,3137.76 2980.14,3137.4 v1(3102.81,3137.4)
NetR21_1: R21.1 R22.1 R338.1 R339.2 | length 268.7
  Top Layer w24: R338.1@2912.02,2893.77 R21.1@2969.84,2893.77 ; R339.2@2913,3047 v1(2923,3047) R22.1@2970.84,3047.02
  Signal Layer 2 w10.5: v1(2923,2894) v1(2923,3047)
NetR29_1: R29.1 R30.1 R297.1 | length 141.2
  Bottom Layer w10: v1(3131.46,2493.04) 3132.84,2494.42 v1(3132.84,2633.66)
NetR31_1: R31.1 R32.1 R284.1 R285.2 | length 339.8
  Top Layer w24: v1(2914.6,2645.66) R31.1@2970.49,2645.66 ; R285.2@2914.62,2645.64 R31.1@2970.51,2645.64 ; R284.1@2916.6,2796.66 2916.75,2796.5 v1(2970.51,2796.5)
  Bottom Layer w13.5: v1(2914.6,2645.66) 2970.51,2701.58 v1(2970.51,2796.5)
NetR33_2: R33.2 R270.2 Y1.3 | length 655
  Top Layer w24: R33.2@5452.97,3047.04 5452.97,2972.16 R270.2@5451.48,2970.66 5451.48,2912.58 ccw(c5551.48,2912.58) 5480.77,2841.87 5529.69,2792.95 ccw(c5600.4,2863.66) 5600.4,2763.66 5893.71,2763.66 Y1.3@5893.97,2763.39
NetR45_1: R45.1 U2.4@5269.91,2979.81 | length 1167.8
  Top Layer w24: v1(6339.55,3101.65) R45.1@6339.55,3153.65
  Bottom Layer w19: U2.4@5269.91,2979.81 5362.47,3072.37 cw(c5433.18,3001.66) 5433.18,3101.66 v1(6339.55,3101.65)
NetR46_1: R46.1 U2.5@5269.91,2879.81 | length 1163.5
  Top Layer w24: R46.1@6339.55,2711.27 v1(6339.55,2758.65)
  Bottom Layer w19: U2.5@5269.91,2879.81 5362.47,2787.24 ccw(c5433.18,2857.95) 5433.18,2757.95 6338.83,2757.95 v1(6339.55,2758.65)
NetR47_1: R47.1 R48.1 R290.1 R291.1 | length 334.4
  Top Layer w20: R47.1@3140.57,2174.35 R47.1@3140.7,2174.47
  Top Layer w24: R290.1@3083.6,2325.66 3083.66,2325.59 R48.1@3140.57,2325.59 3164.04,2325.59 v1(3182.97,2306.66) ; R291.1@3085.6,2173.66 3086.29,2174.35 R47.1@3140.57,2174.35 ; R47.1@3140.7,2174.47 v1(3178.28,2174.47)
  Bottom Layer w13.5: v1(3178.28,2174.47) 3178.28,2301.97 v1(3182.97,2306.66)
NetR49_1: R49.1 R50.1 R298.1 | length 302.8
  Top Layer w24: v1(2811,2345) 2867.69,2345 R49.1@2868.35,2345.66
  Signal Layer 2 w24: v1(2811,2345) 2811,2461.69 2843.97,2494.66 v1(2868.35,2494.66)
  Bottom Layer w24: v1(2811,2345) 2811.34,2344.66 R298.1@2868.35,2344.66
NetR51_2: R51.2 U2.2@5124.24,2879.81 | length 74.8
  Bottom Layer w13.5: R51.2@5052.07,2886.22 U2.2@5117.82,2886.22
  Bottom Layer w19: U2.2@5117.82,2886.22 U2.2@5124.24,2879.81
NetR73_2: R73.2 R76.2 R322.2 R330.1 | length 105.6
  Top Layer w24: R330.1@4424.05,2008.3 4424.05,2007.55 R76.2@4461.3,1970.3 4461.7,1970.3 R73.2@4498.3,1933.7
NetR99_1: R99.1 R214.1 R349.1 U3.28 | length 164.3
  Top Layer w9.84: v1(841.6,3178.97) 841.6,3182.97 862.97,3204.33 U3.28@896.53,3204.33
  Bottom Layer w13.5: v1(841.6,3178.97) 842,3178.57 R99.1@842,3134.62 R214.1@842,3082.62
NetR100_1: R100.1 R213.1 R348.1 U3.5 | length 178.3
  Top Layer w9.84: U3.5@1124.88,3243.7 v1@1161.7,3243.7
  Top Layer w10: v1@1161.7,3243.7 v1(1162,3244)
  Bottom Layer w13.5: v1(1162,3244) 1162,3241 1195,3208 R100.1@1195,3167.62 R213.1@1195,3116.62
NetR103_1: R103.1 R104.1 R106.2 R107.1 R108.2 | length 377.3
  Top Layer w24: R107.1@1556.38,3108.67 R104.1@1609.46,3055.59 ; R104.1@1607.7,3053.84 R106.2@1672.7,3053.84 ; R106.2@1672.96,3054.1 R108.2@1672.96,3291.35
NetR110_2: R110.2 R111.2 R112.2 R113.2 R165.2 | length 372.1
  Top Layer w24: R112.2@1558.87,3520.22 1614.5,3575.85 R111.2@1673.15,3575.85 ; R110.2@1673.21,3341.09 R111.2@1673.21,3575.85
NetR132_1: R132.1 R216.1 R353.1 U4.28 | length 163.3
  Top Layer w9.84: v1@841.35,780.57 841.35,784.57 862.71,805.93 U4.28@896.27,805.93
  Bottom Layer w13.5: v1(840.85,781.07) R132.1@840.85,737.12 840.85,685.78 R216.1@841,685.62
NetR134_1: R134.1 R276.1 R350.2 U23.3 | length 3305.6
  Signal Layer 2 w5.5: v1(2262,2735.37) 2244.5,2717.87 1855.39,2717.87 1828.5,2744.76 1828.5,2832.5 1849.5,2853.5 2224.76,2853.5 2255,2883.74 2255,3358 2291,3394 2700,3394 2730,3364 2730,2605.74 2759.24,2576.5 2877.24,2576.5 2899.49,2554.25 2938.37,2554.25 v1(2957.62,2535)
  Bottom Layer w4.25: U23.3@2082.49,2739.5 2130.92,2739.5 2134,2742.58 2134,2756 2139,2761 2154,2761 2158,2757 2158,2724.75 2164,2718.75 2191.01,2718.75 R276.1@2208,2735.74 2227.37,2716.37 2243,2716.37 v1(2262,2735.37)
  Bottom Layer w13.5: R134.1@2011.62,2739.5 U23.3@2082.49,2739.5
NetR137_1: R137.1 R138.1 R139.2 R140.1 R141.2 | length 377.3
  Top Layer w24: R140.1@1556.12,710.27 R138.1@1609.2,657.19 ; R138.1@1607.45,655.44 R139.2@1672.45,655.44 ; R139.2@1672.7,655.7 R141.2@1672.7,892.94
NetR143_2: R143.2 R144.2 R145.2 R146.2 R168.2 | length 372.1
  Top Layer w24: R145.2@1558.61,1121.82 1614.25,1177.45 R144.2@1672.89,1177.45 ; R143.2@1672.95,942.69 R144.2@1672.95,1177.44
NetR147_1: R147.1 U5.31 | length 111.9
  Top Layer w10: U5.31@5432.04,338.6 v1(5432.04,395.18)
  Bottom Layer w13.5: R147.1@5431.7,340.02 5431.7,394.83 v1(5432.04,395.18)
NetR153_1: R153.1 U5.5 | length 116.6
  Top Layer w10: U5.5@5451.73,661.44 5451.73,718.55 v1(5452.2,719.02)
  Bottom Layer w13.5: R153.1@5427.2,670.51 5427.2,694.02 v1(5452.2,719.02)
NetR160_1: R160.1 R163.1 U7.1 | length 163
  Top Layer w10: R160.1@5785.7,462.02 5840.7,462.02 R163.1@5855.2,447.52
  Top Layer w24: R163.1@5855.2,447.52 5889.7,447.52 5903.96,461.77 U7.1@5936.8,461.77
NetR166_1: R166.1 R169.2 | length 65.6
  Top Layer w10: R166.1@5722.18,4243.52 5723.68,4245.01 R169.2@5787.18,4245.01
NetR170_2: R170.2 U10.8 | length 59.1
  Top Layer w10: R170.2@6327.64,1983.11 6327.9,1983.37 U10.8@6327.9,2042.12
NetR171_2: R171.2 U11.8 | length 59.1
  Top Layer w10: R171.2@6306.21,3553.87 6306.46,3553.62 U11.8@6306.46,3612.37
NetR174_2: R174.2 U10.11 | length 83.7
  Top Layer w10: U10.11@6419.43,2082.48 6446.55,2082.48 R174.2@6486.57,2042.46
NetR175_2: R175.2 U11.11 | length 83.7
  Top Layer w10: U11.11@6398,3652.73 6425.12,3652.73 R175.2@6465.14,3612.71
NetR176_2: R176.2 U10.12 | length 73.6
  Top Layer w10: U10.12@6419.43,2108.07 6470.96,2108.07 R176.2@6486.57,2092.46
NetR177_2: R177.2 U11.12 | length 73.6
  Top Layer w10: U11.12@6398,3678.32 6449.53,3678.32 R177.2@6465.14,3662.71
NetR179_2: R179.2 U12.11 | length 135.6
  Top Layer w8: U12.11@2835.42,4654.3 2850.62,4654.3 2857.79,4647.14 2857.79,4582.04 R179.2@2889.71,4550.12
NetR180_2: R180.2 U12.10 | length 91.8
  Top Layer w8: U12.10@2809.83,4628.71 2809.83,4587.11 2841.71,4555.23 R180.2@2841.71,4550.12
NetR191_1: R191.1 R192.2 U14.1 | length 171.9
  Top Layer w24: R191.1@3998.03,1807.32 3998.03,1760.05 v1(4003.51,1754.57)
  Bottom Layer w8: R192.2@4003.51,1705.08 R192.2@4004.03,1704.57
  Bottom Layer w16: U14.1@3987.56,1814.65 3987.56,1770.51 v1(4003.51,1754.57) R192.2@4003.51,1705.08
NetR191_2: R191.2 R193.1 R195.1 U14.4 | length 212.7
  Top Layer w24: v3@3935.03,1940.94 3935.03,1877.07 R195.1@3957.53,1854.57 R191.2@3998.03,1854.57
  Bottom Layer w8: U14.4@3935.4,1904.21 U14.4@3936.38,1903.23
  Bottom Layer w16: R193.1@3935.4,1977.94 v3(3935.4,1940.94) 3936.38,1939.96 U14.4@3936.38,1903.23
NetR193_2: R193.2 R196.2 R197.2 R201.1 | length 163.8
  Bottom Layer w8: R201.1@3982.65,2027.94 R201.1@3985.03,2030.32 ; R197.2@4039.4,1977.94 R197.2@4040.4,1978.94 ; R196.2@4040.4,2030.32 R196.2@4041.03,2030.94
  Bottom Layer w16: R201.1@3982.65,2027.94 R193.2@3982.65,1977.94 R197.2@4039.4,1977.94 ; R197.2@4040.4,1978.94 R196.2@4040.4,2030.32
NetR194_2: R194.2 R195.2 U14.2 | length 169.3
  Top Layer w24: v1(3946.03,1754.57) 3961.97,1770.51 3961.97,1802.87 R195.2@3957.53,1807.32
  Bottom Layer w16: R194.2@3947.03,1703.57 v1@3947.03,1753.57 ; v1@3953.49,1760.03 3961.97,1768.51 U14.2@3961.97,1814.65
NetR207_1: R207.1 U15.1 | length 55.3
  Top Layer w10: U15.1@4123,299.23 R207.1@4123,354.5
NetR208_2: R208.2 U13.15 | length 102.5
  Top Layer w15: R208.2@3953.64,3021.68 3973.95,3042 U13.15@4047.72,3042
NetR215_1: R215.1 R277.1 R352.1 U4.5 | length 176.3
  Top Layer w9.84: U4.5@1124.62,845.3 v1@1161.44,845.3
  Top Layer w10: v1@1161.44,845.3 v1@1161.74,845.6
  Bottom Layer w13.5: v1(1161.24,846.1) 1161.24,843.1 1194.24,810.1 R277.1@1194.24,769.72 1194.24,721.76 R215.1@1195,721
NetR217_2: R217.2 U5.32 | length 270.9
  Top Layer w10: U5.32@5451.73,338.6 5451.73,293.99 5514.7,231.02 5537.2,231.02
  Top Layer w24: 5537.2,231.02 5594.7,231.02 R217.2@5635.2,190.51
NetR218_1: R218.1 U15.7 | length 69.1
  Top Layer w10: U15.7@4249,279.53 4295.18,279.53 R218.1@4311.38,295.73
NetR219_1: R219.1 U15.6 | length 68.2
  Top Layer w10: U15.6@4249,259.83 4297.28,259.83 R219.1@4311.38,245.73
NetR221_1: R221.1 R226.2 U9.15 | length 166.2
  Top Layer w10: U9.15@5041.47,4321.46 5082.77,4321.46 5101.48,4340.16 R226.2@5135.97,4340.16 R221.1@5199.97,4340.16
NetR228_1: R228.1 R229.2 TP14.1 | length 491.8
  Bottom Layer w13.5: TP14.1@4778.38,4690.56 4655,4567.18 4655,4390 4677.84,4367.16 R228.1@4717.97,4367.16 4718.48,4366.66 R229.2@4785.48,4366.66
NetR231_2: R231.2 U9.7 | length 74
  Top Layer w10: R231.2@4848.47,4301.66 4848.57,4301.76 U9.7@4922.47,4301.76
NetR240_1: R240.1 U16.3 | length 234.9
  Top Layer w7: 2101,2388.54 2101,2385 2111.42,2374.58 2145.46,2374.58 2147.81,2376.92 U16.3@2166.12,2376.92
  Top Layer w12: R240.1@1970.94,2463.2 1985.44,2448.7 2040.84,2448.7 2101,2388.54
NetR241_1: R241.1 U16.4 | length 230.8
  Top Layer w7: 2086.86,2374.39 2090.39,2374.39 2105.21,2359.58 2145.46,2359.58 2147.81,2357.24 U16.4@2166.12,2357.24
  Top Layer w12: R241.1@1970.94,2414.2 1985.44,2428.7 2032.55,2428.7 2086.86,2374.39
NetR242_1: R242.1 U16.6 | length 230.8
  Top Layer w7: 2086.86,2300.71 2090.39,2300.71 2105.21,2315.52 2145.46,2315.52 2147.81,2317.87 U16.6@2166.12,2317.87
  Top Layer w12: R242.1@1970.94,2260.91 1985.44,2246.41 2032.55,2246.41 2086.86,2300.71
NetR243_1: R243.1 U16.7 | length 234.9
  Top Layer w7: 2101,2286.57 2101,2290.1 2111.42,2300.52 2145.46,2300.52 2147.81,2298.18 U16.7@2166.12,2298.18
  Top Layer w12: R243.1@1970.94,2211.91 1985.44,2226.41 2040.84,2226.41 2101,2286.57
NetR262_2: R262.2 R263.1 | length 843.2
  Bottom Layer w4.25: v1(1922.32,2515.53) 1922.32,2457.16 1934.32,2445.16 2008.52,2445.16 2033.5,2420.18 2033.5,2330.84 2070.82,2293.52 2070.82,1905.41 2095.07,1881.16 2159.57,1881.16 R263.1@2180.32,1901.91
NetR264_2: R264.2 R265.1 | length 843.7
  Bottom Layer w4.25: v1(1921.32,2366.28) 1921.32,2423.66 1934.32,2436.66 2005,2436.66 2025,2416.66 2025,2327.32 2062.32,2290 2062.32,1901.88 2091.55,1872.66 2159.57,1872.66 R265.1@2180.32,1851.91
NetR266_2: R266.2 R267.1 | length 952.1
  Top Layer w12: R267.1@2276.07,1871.53 2291.07,1856.53 2291.07,1826.66 v1(2276.57,1812.16)
  Bottom Layer w4.25: v1(1921.32,2309.53) 1921.32,2252.66 1934.32,2239.66 1986.57,2239.66 2027.82,2198.41 2027.82,1864.43 2130.84,1761.41 2280.82,1761.41 2295.94,1776.53 2295.94,1792.78 v1(2276.57,1812.16)
NetR268_2: R268.2 R269.1 | length 965.9
  Top Layer w12: v1(2323.82,1811.41) 2311.07,1824.16 2311.07,1856.53 R269.1@2326.07,1871.53
  Bottom Layer w4.25: v1(1920.32,2161.28) 1920.32,2217.16 1934.32,2231.16 1983.05,2231.16 2019.32,2194.88 2019.32,1860.91 2127.32,1752.91 2284.34,1752.91 2304.44,1773.01 2304.44,1792.03 v1(2323.82,1811.41)
NetR276_2: R276.2 R351.2 U23.4 | length 3232.2
  Signal Layer 2 w5.5: v1(2262,2688.87) 2244.5,2706.37 1850.63,2706.37 1817,2740 1817,2837.26 1844.74,2865 2220,2865 2243.5,2888.5 2243.5,3362.76 2286.24,3405.5 2704.76,3405.5 2741.5,3368.76 2741.5,2610.5 2764,2588 2882,2588 2904.25,2565.75 2938.75,2565.75 v1(2958,2585)
  Bottom Layer w4.25: U23.4@2082.49,2689.5 2142.01,2689.5 2162.76,2710.25 2189,2710.25 2202.88,2696.38 2202.88,2693.63 R276.2@2208,2688.5 2227.37,2707.87 2243,2707.87 v1(2262,2688.87)
NetR294_1: R294.1 U12.4 | length 80.9
  Top Layer w8: R294.1@2624.79,4673.66 2625.11,4673.98 U12.4@2705.5,4673.98
NetR295_2: R295.2 U12.6 | length 91.6
  Top Layer w8: R295.2@2699.71,4550.12 2731.09,4581.51 U12.6@2731.09,4628.71
NetR300_1: R300.1 R301.1 R354.2 U24.3 | length 3320.3
  Top Layer w12: v1(2285,341.13) 2271.75,327.88 2221.59,327.88 2192,298.28 2192,255.72 2219.72,228 2314.41,228 2593,506.59 2593,1068 3006,1481 3006,1898.28 2663,2241.28 2663,2356 2715,2408 2769.82,2408 2782.42,2395.4 R354.2@2807.17,2395.4
  Bottom Layer w4.25: R300.1@2010.62,340.5 U24.3@2080.49,340.5 ; U24.3@2081.49,341.5 2129.92,341.5 2149.67,321.75 2186.25,321.75 R301.1@2206,341.5 2225.37,322.13 2266,322.13 v1(2285,341.13)
NetR301_2: R301.2 R355.2 U24.4 | length 3250.5
  Top Layer w12: v1(2285,294.63) 2271.75,307.88 2229.88,307.88 2212,290 2212,264 2228,248 2306.12,248 2573,514.88 2573,1076.28 2986,1489.28 2986,1890 2643,2233 2643,2364.28 2706.72,2428 2765.4,2428 2782.8,2445.4 R355.2@2807.55,2445.4
  Bottom Layer w4.25: U24.4@2081.49,291.5 2133.5,291.5 2136,289 2136,264 2140.5,259.5 2151.5,259.5 2157,265 2157,303 2167.25,313.25 2187.01,313.25 R301.2@2206,294.26 2225.37,313.63 2266,313.63 v1(2285,294.63)
NetR313_2: R313.2 U18.15 | length 75.8
  Top Layer w15: R313.2@5206.62,1333 5207.62,1332 U18.15@5282,1332
NetR314_2: R314.2 U19.15 | length 102.5
  Top Layer w15: R314.2@5192.62,1689.93 5207.07,1689.93 5238.98,1658.02 U19.15@5281.86,1658.02
NetR315_2: R315.2 U15.2 | length 74.5
  Top Layer w10: R315.2@4053,290.5 4082.5,290.5 4093.47,279.53 U15.2@4123,279.53
NetR316_1: R316.1 R319.1 TP17.1 U20.10 | length 440
  Top Layer w11: TP17.1@3407,136 3482.31,211.31 3625.58,211.31 3626,211.73 R319.1@3658.51,211.73 3658.89,212.11 R316.1@3658.89,278.24 3653.17,278.24 3624.3,307.11 U20.10@3580.38,307.11
NetR317_1: R317.1 TP19.1 U20.11 | length 266.5
  Top Layer w11: U20.11@3580.38,326.8 3610,326.8 3624.44,341.24 R317.1@3658.89,341.24 3689.02,311.1 TP19.1@3828.38,311.1
NetR318_1: R318.1 TP18.1 U20.14 | length 209.6
  Top Layer w11: TP18.1@3502.51,563.24 3580.13,485.61 R318.1@3580.13,454.24 3580.38,453.99 U20.14@3580.38,385.85
NetR325_2: R325.2 R329.1 U22.6 | length 158.9
  Top Layer w10: U22.6@5353.27,2080.43 5402.57,2080.43 5415.62,2067.38 R325.2@5452,2067.38 5452,2017.38 R329.1@5448.62,2014
NetR326_2: R326.2 TP20.1 U22.5 | length 146.3
  Top Layer w8: TP20.1@5214,1979 5213.62,1979.38 R326.2@5213.62,2073 5221.05,2080.43 U22.5@5262.72,2080.43
NetR327_2: R327.2 U21.11 | length 48.8
  Top Layer w11: R327.2@4140.19,2286.81 4149.27,2286.81 U21.11@4177.32,2258.76
NetR328_2: R328.2 U21.10 | length 48.8
  Top Layer w11: R328.2@4163.19,2309.81 4163.19,2300.73 U21.10@4191.24,2272.68
NetR335_2: R335.2 U5.26 | length 90
  Top Layer w8: R335.2@5333.63,248.62 U5.26@5333.62,338.6
NetR340_2: R340.2 U5.21 | length 166.1
  Top Layer w10: U5.21@5260.78,450.81 5309.81,450.81 5328,469 v1(5328,472)
  Bottom Layer w13.5: R340.2@5259,518.76 5281.24,518.76 v1(5328,472)
NetR341_2: R341.2 U5.25 | length 95.1
  Top Layer w10: v1(5302,283) 5313.93,294.93 U5.25@5313.93,338.6
  Bottom Layer w13.5: R341.2@5267.62,282.63 5301.63,282.63 v1(5302,283)
NetRMPCLK1_1: RMPCLK1.1 U3.30 | length 458
  Top Layer w9.84: U3.30@896.53,3164.96 897,3164.49 v1(897,3090)
  Bottom Layer w9.84: RMPCLK1.1@646.8,2880 765,2880 897,3012 v1(897,3090)
NetRMPCLK2_1: RMPCLK2.1 U4.30 | length 452.2
  Top Layer w9.84: U4.30@896.27,766.56 896.35,766.49 v1@896.35,701.57
  Bottom Layer w9.84: RMPCLK2.1@646.04,482.1 765.1,482.1 896,613 v1(896,696)
NetRMPDIR1_1: RMPDIR1.1 U3.32 | length 468.1
  Top Layer w9.84: v1(927.6,3070.97) 941.81,3085.17 U3.32@941.81,3139.37
  Bottom Layer w9.84: RMPDIR1.1@751.8,2750 751.8,2820.27 927.6,2996.07 v1(927.6,3070.97)
NetRMPDIR2_1: RMPDIR2.1 U4.32 | length 468.1
  Top Layer w9.84: v1@927.35,672.57 941.55,686.77 U4.32@941.55,740.97
  Bottom Layer w9.84: RMPDIR2.1@751.04,352.1 751.04,425.04 926.85,600.85 v1(926.85,673.07)
NetU21_1: U21.1 U21.4 U21.5 | length 419.7
  Top Layer w10: U21.1@4244.1,2164.15 4254.91,2153.33 v1(4254.91,2091.91) ; U21.4@4285.85,2205.9 4298,2218.05 4298,2229.95 U21.5@4285.85,2242.1 4322,2278.24 4322,2292 v1(4320,2294)
  Signal Layer 1 w10: v1(4254.91,2091.91) 4320,2157 v1(4320,2294)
